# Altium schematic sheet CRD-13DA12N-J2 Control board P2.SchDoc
size 609 x 508 mm; SheetNumber: 1; SheetTotal: 3
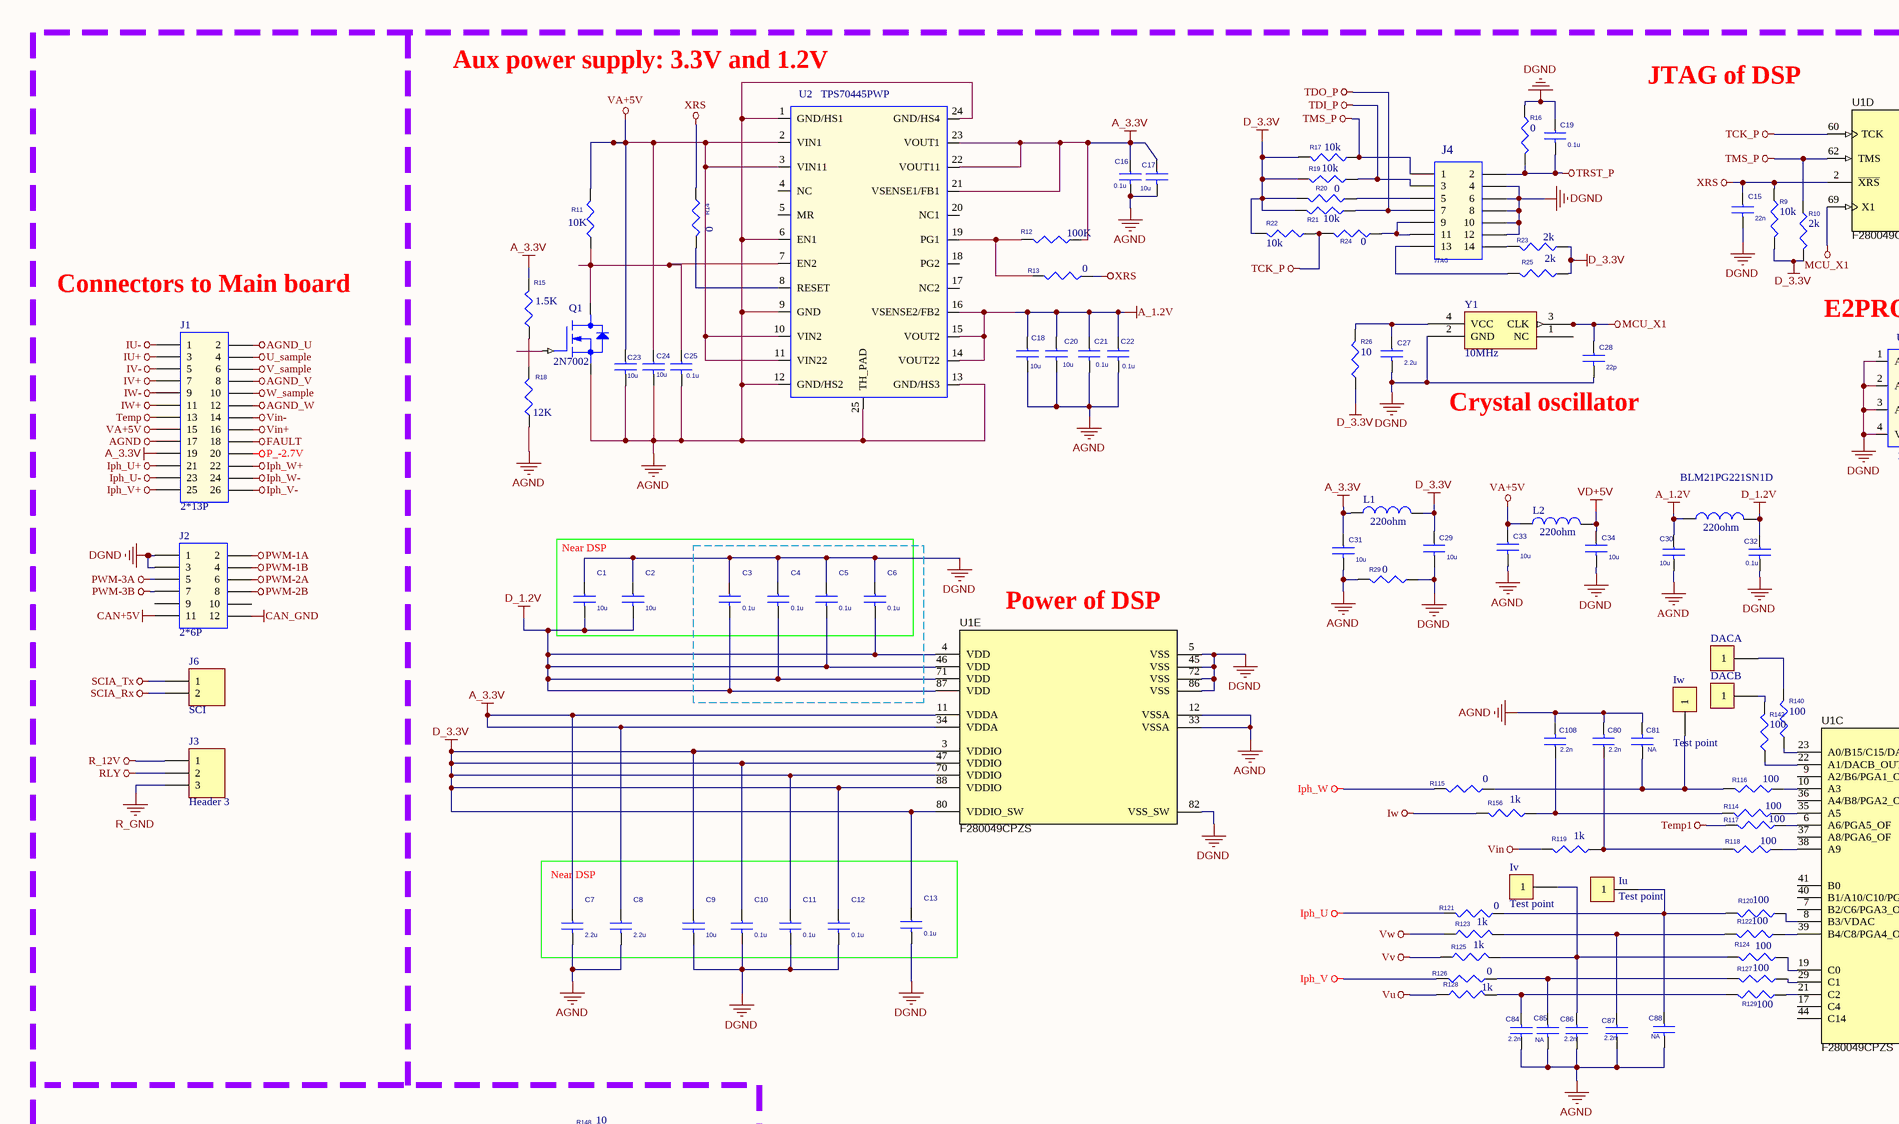
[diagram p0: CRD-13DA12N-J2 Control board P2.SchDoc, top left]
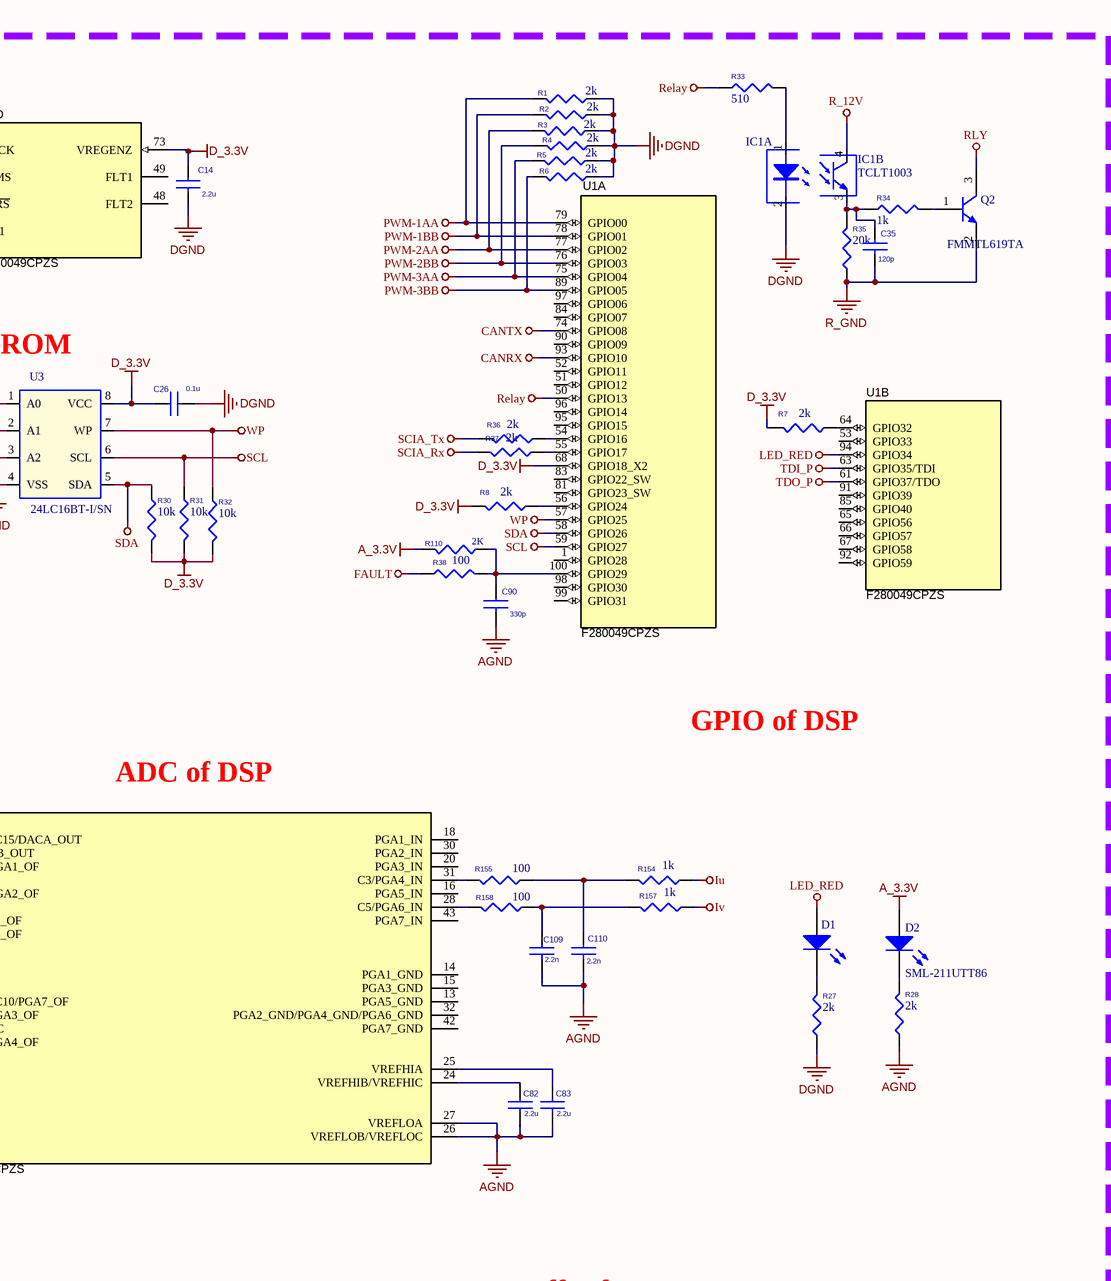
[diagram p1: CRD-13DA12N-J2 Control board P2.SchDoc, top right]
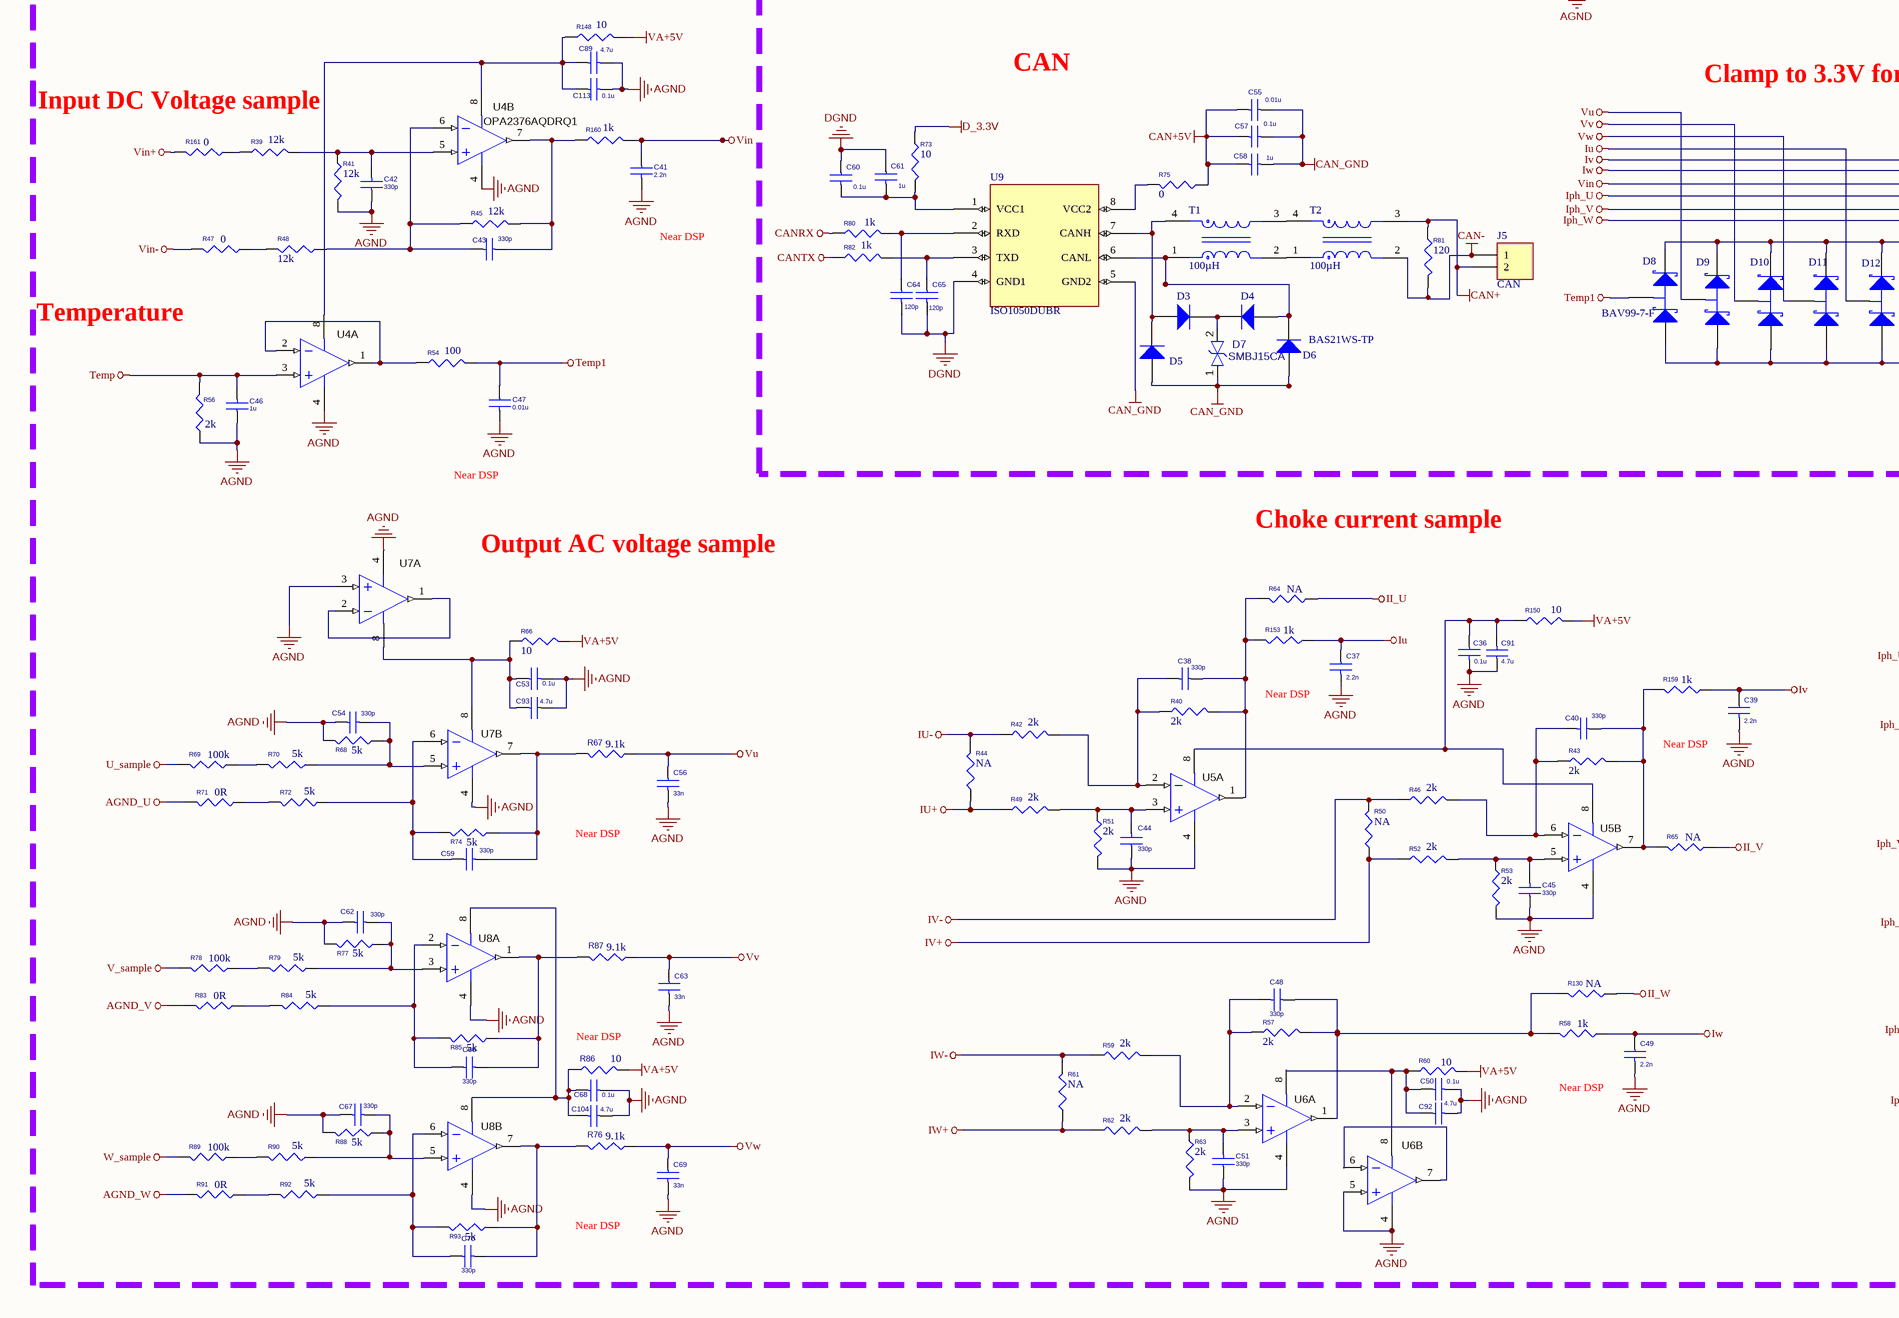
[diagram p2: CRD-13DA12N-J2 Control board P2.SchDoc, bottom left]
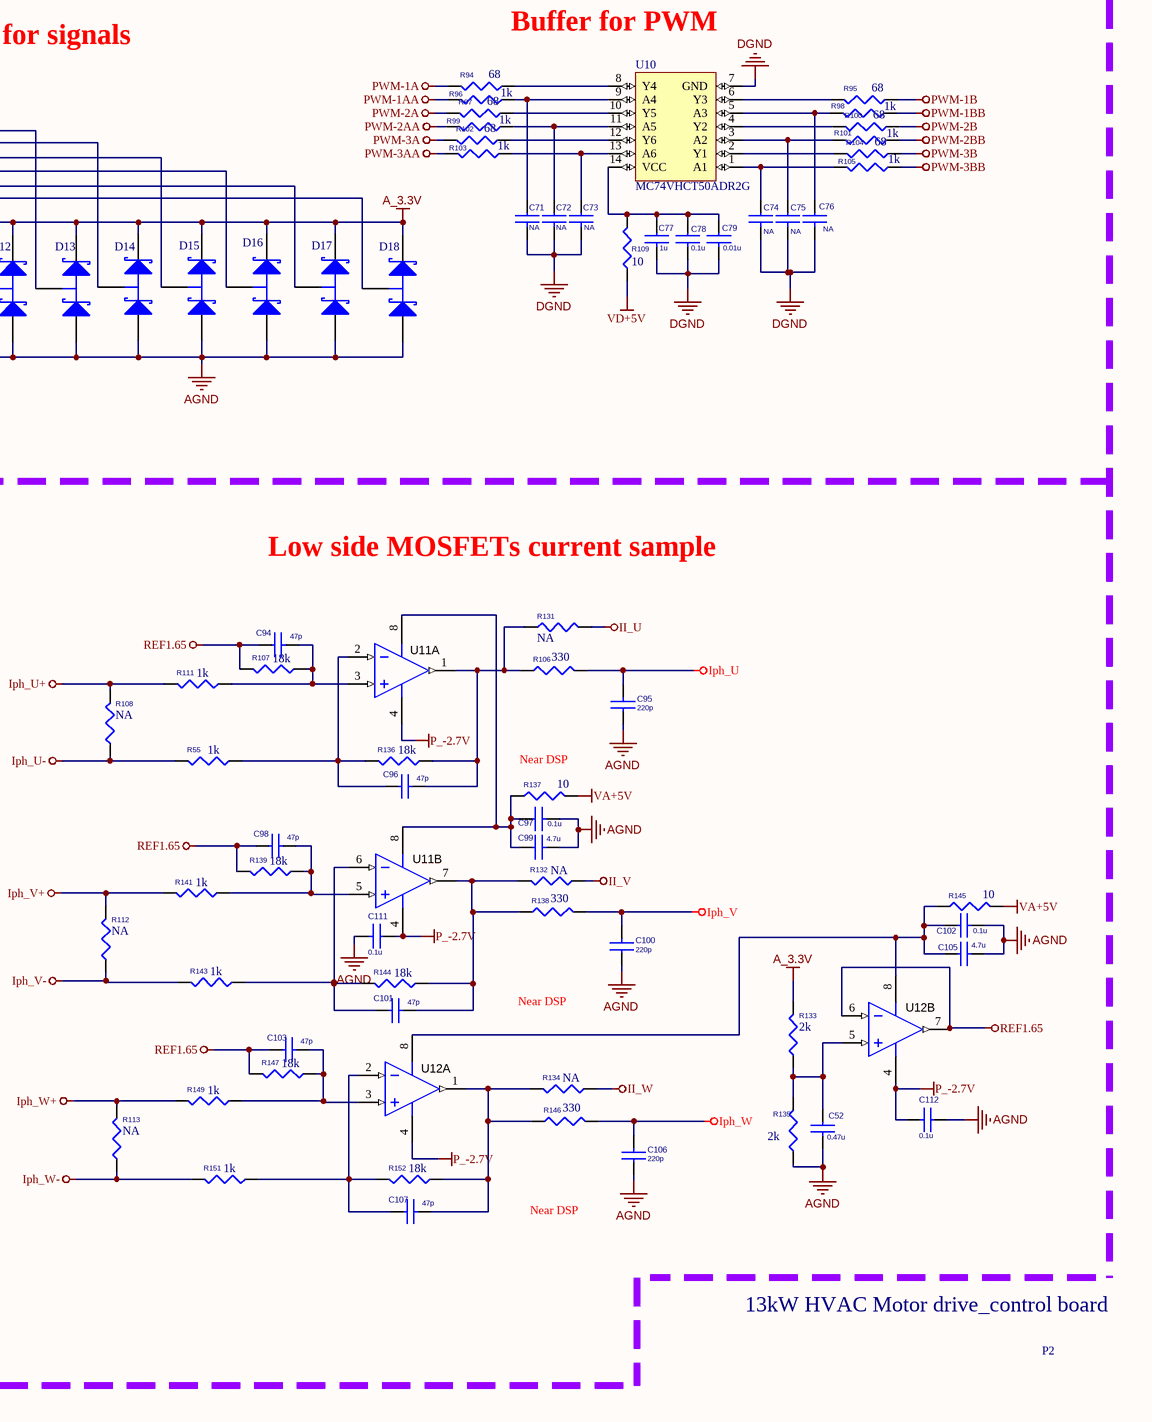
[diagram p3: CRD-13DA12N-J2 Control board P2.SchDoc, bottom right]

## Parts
C1  10u  [C0402]
C2  10u  [C0402]
C3  0.1u  [C0402]
C4  0.1u  [C0402]
C5  0.1u  [C0402]
C6  0.1u  [C0402]
C7  2.2u  [C0402]
C8  2.2u  [C0402]
C9  10u  [C0402]
C10  0.1u  [C0402]
C11  0.1u  [C0402]
C12  0.1u  [C0402]
C13  0.1u  [C0402]
C14  2.2u  [C0402]
C15  22n  [C0402]
C16  0.1u  [C0402]
C17  10u  [C0402]
C18  10u  [C0402]
C19  0.1u  [C0402]
C20  10u  [C0402]
C21  0.1u  [C0402]
C22  0.1u  [C0402]
C23  10u  [C0402]
C24  10u  [C0402]
C25  0.1u  [C0402]
C26  0.1u  [C0402]
C27  2.2u  [C0402]
C28  22p  [C0402]
C29  10u  [C0402]
C30  10u  [C0402]
C31  10u  [C0402]
C32  0.1u  [C0402]
C33  10u  [C0402]
C34  10u  [C0402]
C35  120p  [C0402]
C36  0.1u  [C0402]
C37  2.2n  [C0402]
C38  330p  [C0402]
C39  2.2n  [C0402]
C40  330p  [C0402]
C41  2.2n  [C0402]
C42  330p  [C0402]
C43  330p  [C0402]
C44  330p  [C0402]
C45  330p  [C0402]
C46  1u  [C0402]
C47  0.01u  [C0402]
C48  330p  [C0402]
C49  2.2n  [C0402]
C50  0.1u  [C0402]
C51  330p  [C0402]
C52  0.47u  [C0402]
C53  0.1u  [C0402]
C54  330p  [C0402]
C55  0.01u  [C0402]
C56  33n  [C0402]
C57  0.1u  [C0402]
C58  1u  [C0402]
C59  330p  [C0402]
C60  0.1u  [C0402]
C61  1u  [C0402]
C62  330p  [C0402]
C63  33n  [C0402]
C64  120p  [C0402]
C65  120p  [C0402]
C66  330p  [C0402]
C67  330p  [C0402]
C68  0.1u  [C0402]
C69  33n  [C0402]
C70  330p  [C0402]
C71  NA  [C0402]
C72  NA  [C0402]
C73  NA  [C0402]
C74  NA  [C0402]
C75  NA  [C0402]
C76  NA  [C0402]
C77  1u  [C0402]
C78  0.1u  [C0402]
C79  0.01u  [C0402]
C80  2.2n  [C0402]
C81  NA  [C0402]
C82  2.2u  [C0402]
C83  2.2u  [C0402]
C84  2.2n  [C0402]
C85  NA  [C0402]
C86  2.2n  [C0402]
C87  2.2n  [C0402]
C88  NA  [C0402]
C89  4.7u  [C0402]
C90  330p  [C0402]
C91  4.7u  [C0402]
C92  4.7u  [C0402]
C93  4.7u  [C0402]
C94  47p  [C0402]
C95  220p  [C0402]
C96  47p  [C0402]
C97  0.1u  [C0402]
C98  47p  [C0402]
C99  4.7u  [C0402]
C100  220p  [C0402]
C101  47p  [C0402]
C102  0.1u  [C0402]
C103  47p  [C0402]
C104  4.7u  [C0402]
C105  4.7u  [C0402]
C106  220p  [C0402]
C107  47p  [C0402]
C108  2.2n  [C0402]
C109  2.2n  [C0402]
C110  2.2n  [C0402]
C111  0.1u  [C0402]
C112  0.1u  [C0402]
C113  0.1u  [C0402]
D1  SML-211UTT86  [LED0805]  (value not drawn)
D2  SML-211UTT86  [LED0805]
D3  BAS21WS-TP  [DIOD-SOD323-2-A_V]  (value not drawn)
D4  BAS21WS-TP  [DIOD-SOD323-2-A_V]  (value not drawn)
D5  BAS21WS-TP  [DIOD-SOD323-2-A_V]  (value not drawn)
D6  BAS21WS-TP  [DIOD-SOD323-2-A_V]
D7  SMBJ15CA  [DO214AA]
D8  BAV99-7-F  [SOT-23-3]
D9  BAV99-7-F  [SOT-23-3]  (value not drawn)
D10  BAV99-7-F  [SOT-23-3]  (value not drawn)
D11  BAV99-7-F  [SOT-23-3]  (value not drawn)
D12  BAV99-7-F  [SOT-23-3]  (value not drawn)
D13  BAV99-7-F  [SOT-23-3]  (value not drawn)
D14  BAV99-7-F  [SOT-23-3]  (value not drawn)
D15  BAV99-7-F  [SOT-23-3]  (value not drawn)
D16  BAV99-7-F  [SOT-23-3]  (value not drawn)
D17  BAV99-7-F  [SOT-23-3]  (value not drawn)
D18  BAV99-7-F  [SOT-23-3]  (value not drawn)
DACA  Test point  [TEST_270X100_SMT]  (value not drawn)
DACB  Test point  [TEST_270X100_SMT]  (value not drawn)
IC1  TCLT1003  [tclt1003]  (value not drawn)  (parts A,B of 2)
Iu  Test point  [TEST_270X100_SMT]
Iv  Test point  [TEST_270X100_SMT]
Iw  Test point  [TEST_270X100_SMT]
J1  2*13P  [HDR2X13H-254MM-90-OP]
J2  2*6P  [HDR2X6H-254MM-90-OP]
J3  Header 3  [HDR1X3-254MM]
J4  JTAG  [HDR2X7H-254MM-90]
J5  CAN  [HDR1X2H-254MM]
J6  SCI  [HDR1X2H-254MM]
L1  value 220ohm  [6-0805_L]  (hidden comment: BLM21PG221SN1D)
L2  value 220ohm  [6-0805_L]  (hidden comment: BLM21PG221SN1D)
L3  BLM21PG221SN1D  value 220ohm  [6-0805_L]
Q1  2N7002  [SOT-23-3]
Q2  FMMTL619TA  [SOT-23-3]
R1  2k  [0402]
R2  2k  [0402]
R3  2k  [0402]
R4  2k  [0402]
R5  2k  [0402]
R6  2k  [0402]
R7  2k  [0402]
R8  2k  [0402]
R9  10k  [0402]
R10  2k  [0402]
R11  10K  [0402]
R12  100K  [0402]
R13  0  [0402]
R14  0  [0402]
R15  1.5K  [0402]
R16  0  [0402]
R17  10k  [0402]
R18  12K  [0402]
R19  10k  [0402]
R20  0  [0402]
R21  10k  [0402]
R22  10k  [0402]
R23  2k  [0402]
R24  0  [0402]
R25  2k  [0402]
R26  10  [0402]
R27  2k  [0402]
R28  2k  [0402]
R29  0  [0402]
R30  10k  [0402]
R31  10k  [0402]
R32  10k  [0402]
R33  510  [0402]
R34  1k  [0402]
R35  20k  [0402]
R36  2k  [0402]
R37  2k  [0402]
R38  100  [0402]
R39  12k  [R1206]
R40  2k  [0402]
R41  12k  [0402]
R42  2k  [0402]
R43  2k  [0402]
R44  NA  [0402]
R45  12k  [0402]
R46  2k  [0402]
R47  0  [R1206]
R48  12k  [R1206]
R49  2k  [0402]
R50  NA  [0402]
R51  2k  [0402]
R52  2k  [0402]
R53  2k  [0402]
R54  100  [0402]
R55  1k  [0402]
R56  2k  [0402]
R57  2k  [0402]
R58  1k  [0402]
R59  2k  [0402]
R60  10  [0402]
R61  NA  [0402]
R62  2k  [0402]
R63  2k  [0402]
R64  NA  [0402]
R65  NA  [0402]
R66  10  [0402]
R67  9.1k  [0402]
R68  5k  [0402]
R69  100k  [R1206]
R70  5k  [R1206]
R71  0R  [R1206]
R72  5k  [R1206]
R73  10  [0402]
R74  5k  [0402]
R75  0  [0402]
R76  9.1k  [0402]
R77  5k  [0402]
R78  100k  [R1206]
R79  5k  [R1206]
R80  1k  [0402]
R81  120  [R0603]
R82  1k  [0402]
R83  0R  [R1206]
R84  5k  [R1206]
R85  5k  [0402]
R86  10  [0402]
R87  9.1k  [0402]
R88  5k  [0402]
R89  100k  [R1206]
R90  5k  [R1206]
R91  0R  [R1206]
R92  5k  [R1206]
R93  5k  [0402]
R94  68  [0402]
R95  68  [0402]
R96  1k  [0402]
R97  68  [0402]
R98  1k  [0402]
R99  1k  [0402]
R100  68  [0402]
R101  1k  [0402]
R102  68  [0402]
R103  1k  [0402]
R104  68  [0402]
R105  1k  [0402]
R106  330  [0402]
R107  18k  [0402]
R108  NA  [0402]
R109  10  [0402]
R110  2K  [0402]
R111  1k  [0402]
R112  NA  [0402]
R113  NA  [0402]
R114  100  [0402]
R115  0  [0402]
R116  100  [0402]
R117  100  [0402]
R118  100  [0402]
R119  1k  [0402]
R120  100  [0402]
R121  0  [0402]
R122  100  [0402]
R123  1k  [0402]
R124  100  [0402]
R125  1k  [0402]
R126  0  [0402]
R127  100  [0402]
R128  1k  [0402]
R129  100  [0402]
R130  NA  [0402]
R131  NA  [0402]
R132  NA  [0402]
R133  2k  [0402]
R134  NA  [0402]
R135  2k  [0402]
R136  18k  [0402]
R137  10  [0402]
R138  330  [0402]
R139  18k  [0402]
R140  100  [0402]
R141  1k  [0402]
R142  100  [0402]
R143  1k  [0402]
R144  18k  [0402]
R145  10  [0402]
R146  330  [0402]
R147  18k  [0402]
R148  10  [0402]
R149  1k  [0402]
R150  10  [0402]
R151  1k  [0402]
R152  18k  [0402]
R153  1k  [0402]
R154  1k  [0402]
R155  100  [0402]
R156  1k  [0402]
R157  1k  [0402]
R158  100  [0402]
R159  1k  [0402]
R160  1k  [0402]
R161  0  [R1206]
T1  AMCW4532B-2-101T: 100µH  [T1-1812]  (hidden comment: DLW43SH101XK2L)
T2  AMCW4532B-2-101T: 100µH  [T1-1812]  (hidden comment: DLW43SH101XK2L)
U1  F280049CPZS  [PZ0100A_N]  (parts A,B,C,D,E of 5)
U2  TPS70445PWP  [TPS70445PWP]
U3  24LC16BT-I/SN  [8SOIC]
U4  OPA2376AQDRQ1  [8SOIC]  (value not drawn)  (parts A,B of 2)
U5  OPA2376AQDRQ1  [8SOIC]  (value not drawn)  (parts A,B of 2)
U6  OPA2376AQDRQ1  [8SOIC]  (value not drawn)  (parts A,B of 2)
U7  OPA2376AQDRQ1  [8SOIC]  (value not drawn)  (parts A,B of 2)
U8  OPA2376AQDRQ1  [8SOIC]  (value not drawn)  (parts A,B of 2)
U9  ISO1050DUBR  [8-SOP]
U10  MC74VHCT50ADR2G  [14SOIC]
U11  OPA2836IDR  [8SOIC]  (value not drawn)  (parts A,B of 2)
U12  OPA2836IDR  [8SOIC]  (value not drawn)  (parts A,B of 2)
Y1  10MHz  [TBD-Footprint-1]

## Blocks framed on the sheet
Near DSP: C1-C6
Near DSP: C7-C13

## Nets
A_1.2V: C18.1 C20.1 C21.1 C22.1 C30.1 L3.1 U2.14(VOUT22) U2.15(VOUT2) U2.16(VSENSE2/FB2)
A_3.3V: C7.1 C8.1 C16.1 C17.1 C31.1 D2.1(A) D8.2(K) D9.2(K) D10.2(K) D11.2(K) D12.2(K) D13.2(K) D14.2(K) D15.2(K) D16.2(K) D17.2(K) D18.2(K) J1.19 L1.1 R12.1 R15.2 R110.2 R133.2 U1.11(VDDA) U1.34(VDDA) U2.21(VSENSE1/FB1) U2.22(VOUT11) U2.23(VOUT1)
AGND: C7.2 C8.2 C16.2 C17.2 C18.2 C20.2 C21.2 C22.2 C23.2 C24.2 C25.2 C30.2 C31.2 C33.2 C36.2 C37.2 C39.2 C41.2 C42.1 C44.1 C45.1 C46.1 C47.2 C49.2 C50.2 C51.1 C52.2 C53.2 C54.1 C56.2 C62.1 C63.2 C67.1 C68.2 C69.2 C80.2 C81.2 C82.2 C83.2 C84.2 C85.2 C86.2 C87.2 C88.2 C89.2 C90.2 C91.1 C92.2 C93.2 C95.1 C97.2 C99.2 C100.1 C102.2 C104.2 C105.2 C106.1 C108.2 C109.2 C110.2 C111.2 C112.1 C113.2 D8.1(A) D9.1(A) D10.1(A) D11.1(A) D12.1(A) D13.1(A) D14.1(A) D15.1(A) D16.1(A) D17.1(A) D18.1(A) J1.17 Q1.2(SOURCE) R18.1 R28.1 R29.2 R41.2 R51.2 R53.2 R56.1 R63.2 R68.2 R77.2 R88.2 R135.1 U1.12(VSSA) U1.26(VREFLOB/VREFLOC) U1.27(VREFLOA) U1.33(VSSA) U2.1(GND/HS1) U2.6(EN1) U2.9(GND) U2.12(GND/HS2) U2.13(GND/HS3) U2.24(GND/HS4) U2.25(TH_PAD) U4.4(V-) U5.4(V-) U6.4(V-) U6.5(IN_B+) U7.3(IN_A+) U7.4(V-) U8.4(V-)
AGND_U: J1.2 R71.2
AGND_V: J1.8 R83.2
AGND_W: J1.12 R91.2
CAN+: J5.2 R81.1 T2.3
CAN+5V: C55.1 C57.1 C58.1 J2.11 R75.1
CAN-: J5.1 R81.2 T2.2
CAN_GND: C55.2 C57.2 C58.2 D5.1(A) D6.1(A) D7.1(A) J2.12 U9.5(GND2)
CANRX: R80.1 U1.93(GPIO10)
CANTX: R82.1 U1.74(GPIO08)
D_1.2V: C1.2 C2.2 C3.2 C4.2 C5.2 C6.2 C32.1 L3.2 U1.4(VDD) U1.46(VDD) U1.71(VDD) U1.87(VDD)
D_3.3V: C9.1 C10.1 C11.1 C12.1 C13.1 C14.1 C26.1 C29.1 L1.2 R7.2 R8.2 R9.2 R10.2 R17.2 R19.2 R20.2 R21.2 R22.2 R23.1 R25.1 R26.1 R30.2 R31.2 R32.2 R73.1 U1.3(VDDIO) U1.47(VDDIO) U1.68(GPIO18_X2) U1.70(VDDIO) U1.73(VREGENZ) U1.80(VDDIO_SW) U1.88(VDDIO) U3.8(VCC)
DGND: C1.1 C2.1 C3.1 C4.1 C5.1 C6.1 C9.2 C10.2 C11.2 C12.2 C13.2 C14.2 C15.2 C19.1 C26.2 C27.2 C28.2 C29.2 C32.2 C34.2 C60.1 C61.1 C64.2 C65.2 C71.2 C72.2 C73.2 C74.2 C75.2 C76.2 C77.2 C78.2 C79.2 IC1.2 J2.1 J2.3 J4.4 J4.6 J4.8 J4.10 J4.12 R1.1 R2.1 R3.1 R4.1 R5.1 R6.1 R16.1 R27.1 R29.1 U1.5(VSS) U1.45(VSS) U1.72(VSS) U1.82(VSS_SW) U1.86(VSS) U3.1(A0) U3.2(A1) U3.3(A2) U3.4(VSS) U9.4(GND1) U10.7(GND) Y1.2(GND)
FAULT: J1.18 R38.1
II_U: R64.1 R131.2
II_V: R65.1 R132.1
II_W: R130.1 R134.1
Iph_U: C95.2 D16.3(C) R106.2 R121.2
Iph_U+: J1.21 R108.2 R111.2
Iph_U-: J1.23 R55.2 R108.1
Iph_V: C100.2 D17.3(C) R126.2 R138.2
Iph_V+: J1.25 R112.2 R141.2
Iph_V-: J1.26 R112.1 R143.2
Iph_W: C106.2 D18.3(C) R115.2 R146.2
Iph_W+: J1.22 R113.2 R149.2
Iph_W-: J1.24 R113.1 R151.2
Iu: C37.1 D12.3(C) R153.1 R154.1
IU+: J1.3 R44.1 R49.1
IU-: J1.1 R42.1 R44.2
Iv: C39.1 D13.3(C) R157.1 R159.1
IV+: J1.7 R50.1 R52.1
IV-: J1.5 R46.1 R50.2
Iw: C49.1 D14.3(C) R58.1 R156.2
IW+: J1.11 R61.1 R62.1
IW-: J1.9 R59.1 R61.2
LED_RED: D1.1(A) U1.94(GPIO34)
MCU_X1: C28.1 U1.69(X1) Y1.3(CLK)
P_-2.7V: C111.1 C112.2 J1.20 U11.4(V-) U12.4(V-)
PWM-1A: J2.2 R94.2
PWM-1AA: R1.2 R96.1 U1.79(GPIO00)
PWM-1B: J2.4 R95.1
PWM-1BB: R2.2 R98.1 U1.78(GPIO01)
PWM-2A: J2.6 R97.2
PWM-2AA: R3.2 R99.1 U1.77(GPIO02)
PWM-2B: J2.8 R100.1
PWM-2BB: R4.2 R101.1 U1.76(GPIO03)
PWM-3A: J2.5 R102.2
PWM-3AA: R5.2 R103.1 U1.75(GPIO04)
PWM-3B: J2.7 R104.1
PWM-3BB: R6.2 R105.2 U1.89(GPIO05)
R_12V: IC1.4 J3.1
R_GND: C35.2 J3.3 Q2.2 R35.1
REF1.65: C94.1 C98.1 C103.1 R107.2 R139.2 R147.2 U12.6(IN_B-) U12.7(OUT_B)
Relay: R33.1 U1.50(GPIO13)
RLY: J3.2 Q2.3
SCIA_Rx: J6.2 R37.2
SCIA_Tx: J6.1 R36.2
SCL: R31.1 U1.59(GPIO27) U3.6(SCL)
SDA: R30.1 U1.58(GPIO26) U3.5(SDA)
TCK_P: R22.1 R24.2 U1.60(TCK)
TDI_P: J4.3 R19.1 U1.63(GPIO35/TDI)
TDO_P: J4.7 R21.1 U1.61(GPIO37/TDO)
Temp: C46.2 J1.13 R56.2 U4.3(IN_A+)
Temp1: C47.1 D8.3(C) R54.2 R117.2
TMS_P: J4.1 R10.1 R17.1 U1.62(TMS)
TRST_P: C19.2 J4.2 R16.2
U_sample: J1.4 R69.2
V_sample: J1.6 R78.2
VA+5V: C23.1 C24.1 C33.1 J1.15 L2.1 R11.2 R60.2 R66.2 R86.2 R137.2 R145.2 R148.2 R150.2 U2.2(VIN1) U2.3(VIN11) U2.10(VIN2) U2.11(VIN22)
VD+5V: C34.1 L2.2 R109.1
Vin: C41.1 D15.3(C) R119.2 R160.2
Vin+: J1.16 R161.2
Vin-: J1.14 R47.2
Vu: C56.1 D9.3(C) R67.1 R128.2
Vv: C63.1 D10.3(C) R87.1 R125.2
Vw: C69.1 D11.3(C) R76.1 R123.2
W_sample: J1.10 R89.2
WP: R32.1 U1.57(GPIO25) U3.7(WP)
XRS: C15.1 R9.1 R13.1 R14.1 U1.2(~{XRS})
NetC25_1: C25.1 Q1.3(DRAIN) R11.1 U2.7(EN2)
NetC27_1: C27.1 R26.2 Y1.4(VCC)
NetC35_1: C35.1 IC1.3 R34.1 R35.2
NetC36_1: C36.1 C91.2 R150.1 U5.8(V+)
NetC38_1: C38.1 R40.2 R64.2 R153.2 U5.1(OUT_A)
NetC38_2: C38.2 R40.1 R42.2 U5.2(IN_A-)
NetC40_1: C40.1 R43.2 R65.2 R159.2 U5.7(OUT_B)
NetC40_2: C40.2 R43.1 R46.2 U5.6(IN_B-)
NetC42_2: C42.2 R39.2 R41.1 U4.5(IN_B+)
NetC43_1: C43.1 R45.2 R160.1 U4.7(OUT_B)
NetC43_2: C43.2 R45.1 R48.1 U4.6(IN_B-)
NetC44_2: C44.2 R49.2 R51.1 U5.3(IN_A+)
NetC45_2: C45.2 R52.2 R53.1 U5.5(IN_B+)
NetC48_1: C48.1 R57.2 R58.2 R130.2 U6.1(OUT_A)
NetC48_2: C48.2 R57.1 R59.2 U6.2(IN_A-)
NetC50_1: C50.1 C92.1 R60.1 U6.8(V+)
NetC51_2: C51.2 R62.2 R63.1 U6.3(IN_A+)
NetC52_1: C52.1 R133.1 R135.2 U12.5(IN_B+)
NetC53_1: C53.1 C93.1 R66.1 U7.8(V+)
NetC54_2: C54.2 R68.1 R70.1 U7.5(IN_B+)
NetC59_1: C59.1 R72.1 R74.2 U7.6(IN_B-)
NetC59_2: C59.2 R67.2 R74.1 U7.7(OUT_B)
NetC60_2: C60.2 C61.2 R73.2 U9.1(VCC1)
NetC62_2: C62.2 R77.1 R79.1 U8.3(IN_A+)
NetC64_1: C64.1 R80.2 U9.2(RXD)
NetC65_1: C65.1 R82.2 U9.3(TXD)
NetC66_1: C66.1 R84.1 R85.2 U8.2(IN_A-)
NetC66_2: C66.2 R85.1 R87.2 U8.1(OUT_A)
NetC67_2: C67.2 R88.1 R90.1 U8.5(IN_B+)
NetC68_1: C68.1 C104.1 R86.1 U8.8(V+)
NetC70_1: C70.1 R92.1 R93.2 U8.6(IN_B-)
NetC70_2: C70.2 R76.2 R93.1 U8.7(OUT_B)
NetC71_1: C71.1 R96.2 U10.9(A4)
NetC72_1: C72.1 R99.2 U10.11(A5)
NetC73_1: C73.1 R103.2 U10.13(A6)
NetC74_1: C74.1 R105.1 U10.1(A1)
NetC75_1: C75.1 R101.2 U10.3(A2)
NetC76_1: C76.1 R98.2 U10.5(A3)
NetC77_1: C77.1 C78.1 C79.1 R109.2 U10.14(VCC)
NetC80_1: C80.1 R118.2 R119.1
NetC81_1: C81.1 Iw.1 R115.1 R116.2
NetC82_1: C82.1 U1.24(VREFHIB/VREFHIC)
NetC83_1: C83.1 U1.25(VREFHIA)
NetC84_1: C84.1 R128.1 R129.2
NetC85_1: C85.1 R126.1 R127.2
NetC86_1: C86.1 Iv.1 R124.2 R125.1
NetC87_1: C87.1 R122.2 R123.1
NetC88_1: C88.1 Iu.1 R120.2 R121.1
NetC89_1: C89.1 C113.1 R148.1 U4.8(V+)
NetC90_1: C90.1 R38.2 R110.1 U1.100(GPIO29)
NetC94_2: C94.2 R107.1 R111.1 U11.3(IN_A+)
NetC96_1: C96.1 R55.1 R136.2 U11.2(IN_A-)
NetC96_2: C96.2 R106.1 R131.1 R136.1 U11.1(OUT_A)
NetC97_1: C97.1 C99.1 R137.1 U11.8(V+)
NetC98_2: C98.2 R139.1 R141.1 U11.5(IN_B+)
NetC101_1: C101.1 R143.1 R144.2 U11.6(IN_B-)
NetC101_2: C101.2 R132.2 R138.1 R144.1 U11.7(OUT_B)
NetC102_1: C102.1 C105.1 R145.1 U12.8(V+)
NetC103_2: C103.2 R147.1 R149.1 U12.3(IN_A+)
NetC107_1: C107.1 R151.1 R152.2 U12.2(IN_A-)
NetC107_2: C107.2 R134.2 R146.1 R152.1 U12.1(OUT_A)
NetC108_1: C108.1 R114.2 R156.1
NetC109_1: C109.1 R157.2 R158.1
NetC110_1: C110.1 R154.2 R155.1
NetD1_2: D1.2(K) R27.2
NetD2_2: D2.2(K) R28.2
NetD3_1: D3.1(A) D5.2(K) T1.4 U9.7(CANH)
NetD3_2: D3.2(K) D4.2(K) D7.2(A)
NetD4_1: D4.1(A) D6.2(K) T1.1 U9.6(CANL)
NetDACA_1: DACA.1 R140.2
NetDACB_1: DACB.1 R142.2
NetIC1_1: IC1.1 R33.2
NetJ4_5: J4.5 R20.1
NetJ4_9: J4.9 J4.11 R24.1
NetJ4_13: J4.13 R25.2
NetJ4_14: J4.14 R23.2
NetQ2_1: Q2.1 R34.2
NetR7_1: R7.1 U1.64(GPIO32)
NetR8_1: R8.1 U1.56(GPIO24)
NetR12_2: R12.2 R13.2 U2.19(PG1)
NetR14_2: R14.2 U2.8(RESET)
NetR15_1: R15.1 R18.2
NetR36_1: R36.1 U1.54(GPIO16)
NetR37_1: R37.1 U1.55(GPIO17)
NetR39_1: R39.1 R161.1
NetR47_1: R47.1 R48.2
NetR54_1: R54.1 U4.1(OUT_A) U4.2(IN_A-)
NetR69_1: R69.1 R70.2
NetR71_1: R71.1 R72.2
NetR75_2: R75.2 U9.8(VCC2)
NetR78_1: R78.1 R79.2
NetR83_1: R83.1 R84.2
NetR89_1: R89.1 R90.2
NetR91_1: R91.1 R92.2
NetR94_1: R94.1 U10.8(Y4)
NetR95_2: R95.2 U10.6(Y3)
NetR97_1: R97.1 U10.10(Y5)
NetR100_2: R100.2 U10.4(Y2)
NetR102_1: R102.1 U10.12(Y6)
NetR104_2: R104.2 U10.2(Y1)
NetR114_1: R114.1 U1.35(A5)
NetR116_1: R116.1 U1.10(A3)
NetR117_1: R117.1 U1.6(A6/PGA5_OF)
NetR118_1: R118.1 U1.38(A9)
NetR120_1: R120.1 U1.8(B3/VDAC)
NetR122_1: R122.1 U1.39(B4/C8/PGA4_OF)
NetR124_1: R124.1 U1.19(C0)
NetR127_1: R127.1 U1.29(C1)
NetR129_1: R129.1 U1.21(C2)
NetR140_1: R140.1 U1.23(A0/B15/C15/DACA_OUT)
NetR142_1: R142.1 U1.22(A1/DACB_OUT)
NetR155_2: R155.2 U1.31(C3/PGA4_IN)
NetR158_2: R158.2 U1.28(C5/PGA6_IN)
NetT1_2: T1.2 T2.1
NetT1_3: T1.3 T2.4
NetU6_6: U6.6(IN_B-) U6.7(OUT_B)
NetU7_1: U7.1(OUT_A) U7.2(IN_A-)

Not connected (* = marked no-connect by the designer): J2 9 10; Q1 1(GATE); U1 1(GPIO28) 7(B2/C6/PGA3_OF) 9(A2/B6/PGA1_OF) 13(PGA5_GND) 14(PGA1_GND) 15(PGA3_GND) 16(PGA5_IN) 17(C4) 18(PGA1_IN) 20(PGA3_IN) 30(PGA2_IN) 32(PGA2_GND/PGA4_GND/PGA6_GND) 36(A4/B8/PGA2_OF) 37(A8/PGA6_OF) 40(B1/A10/C10/PGA7_OF) 41(B0) 42(PGA7_GND) 43(PGA7_IN) 44(C14) 48(FLT2) 49(FLT1) 51(GPIO12) 52(GPIO11) 53(GPIO33) 65(GPIO56) 66(GPIO57) 67(GPIO58) 81(GPIO23_SW) 83(GPIO22_SW) 84(GPIO07) 85(GPIO40) 90(GPIO09) 91(GPIO39) 92(GPIO59) 95(GPIO15) 96(GPIO14) 97(GPIO06) 98(GPIO30) 99(GPIO31); U2 4(NC) 5(MR) 17(NC2) 18(PG2) 20(NC1); Y1 1(NC)

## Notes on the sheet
- (near U2) Aux power supply: 3.3V and 1.2V
- JTAG of DSP
- (near J1) Connectors to Main board
- E2PROM
- (near C28) Crystal oscillator
- (near U1) Power of DSP
- GPIO of DSP
- (near U1) ADC of DSP
- Buffer for PWM
- Input DC Voltage sample
- CAN
- Clamp to 3.3V for signals
- Near DSP
- Temperature
- Output AC voltage sample
- Choke current sample
- Low side MOSFETs current sample
- (near R137) Near DSP
- (near R86) Near DSP
- 13kW HVAC Motor drive_control board
- P2

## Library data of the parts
C1 C2 C9 C17 C18 C20 C23 C24 C29-C31 C33 C34 = CAP NP_Dup1: CAP CER 10UF 10V X5R 0402; PartNumber: CL05A106MP5NUNC; Manufactur: Samsung Electro-Mechanics
C3-C6 C10-C13 C16 C19 C21 C22 C25 C26 C32 C36 C50 C53 C57 C60 C68 C78 C97 C102 C111-C113 = CAP NP_Dup1: CAP CER 0.1UF 25V X7R 0402; PartNumber: C0402C104K3RAC7867; Manufactur: KEMET
C7 C8 C14 C27 C82 C83 = CAP NP_Dup1: CAP CER 2.2UF 10V X5R 0402; Manufactur: KEMET; PartNumber: C0402C225M8PAC7867
C15 = CAP NP_Dup1: CAP CER 0.022UF 50V X7R 0402; PartNumber: C0402C223K5RAC7411; Manufactur: KEMET
C28 = CAP NP_Dup1: CAP CER 22PF 50V C0G/NP0 0402; PartNumber: C0402C220J5GAC7411; Manufactur: KEMET
C35 C64 C65 = CAP NP_Dup1: CAP CER 120PF 25V C0G/NP0 0402; PartNumber: C0402C121J3GAC7867; Manufactur: KEMET
C37 C39 C41 C49 C80 C81 C84-C88 C108-C110 = CAP NP_Dup1: CAP CER 2200PF 50V X7R 0402; PartNumber: C0402C222K5RAC7867; Manufactur: KEMET
C38 C40 C42-C45 C48 C51 C54 C59 C62 C66 C67 C70 = CAP NP_Dup1: CAP CER 330PF 25V X7R 0402; PartNumber: C0402C331K3RAC7867; Manufactur: KEMET
C46 C58 C61 C77 = CAP NP_Dup1: CAP CER 1UF 10V X5R 0402; PartNumber: C0402C105K8PAC7411; Manufactur: KEMET
C47 C55 C79 = CAP NP_Dup1: CAP CER 0.012UF 16V X7R 0402; PartNumber: C0402C123K4RAC7867; Manufactur: KEMET
C52 = CAP NP_Dup1: CAP CER 0.47UF 25V X5R 0402; PartNumber: C1005X5R1E474K050BB; Manufactur: TDK
C56 C63 C69 = CAP NP_Dup1: CAP CER 0.033uF 25V X7R 0402; PartNumber: C0402C333K3RECTU; Manufactur: KEMET
C71-C76 = CAP NP_Dup1: CAP CER 100PF 25V X7R 0402; Manufactur: KEMET; PartNumber: C0402C101K3RAC7867
C89 C91-C93 C99 C104 C105 = CAP NP_Dup1: CAP CER 4.7UF 10V X5R 0402; PartNumber: CL05A475MP5NRNC; Manufactur: Samsung Electro-Mechanics
C90 = CAP NP_Dup1: CAP CER 330PF 25V C0G/NP0 0402; PartNumber: C0402C331J3GAC7867; Manufactur: KEMET
C94 C96 C98 C101 C103 C107 = CAP NP_Dup1: CAP CER 47PF 25V X7R 0402; PartNumber: C0402C470K3RAC7867; Manufactur: KEMET
C95 C100 C106 = CAP NP_Dup1: CAP CER 220PF 25V X7R 0402; PartNumber: C0402C221K3RAC7867; Manufactur: KEMET
D1 D2 = LED0: LED RED CLEAR 0805 SMD; Manufactur: Rohm Semiconductor
D3-D6 = CMP-004-00002-1: DIODE GEN PURP 250V 200MA SOD323; Manufacturer: Diodes Inc; Manufactur: Micro Commercial Co; Peak Reverse Current: 1uA; Forward Voltage: 1.25V; Recovery Time: 4ns; Max Surge Current: 2A; Forward Current: 3dA; Elements: 1
D7 = CMP-004-00030-2: TVS DIODE 15V 24.4V DO214AA; Manufactur: Littelfuse Inc.; Manufacturer Part Number: ESDALC5-1BM2
D8-D18 = CMP-004-00011-1: DIODE ARRAY GP 75V 300MA SOT23-3; Manufacturer: Diodes Inc; Manufacturer: Diodes; Manufacturer Part Number: BAS70-04-7-F; Manufactur: Micro Commercial Co; Power: 200mW; Peak Reverse Current: 0.1uA; Forward Voltage: 1V; Element Configuration: CommonCathode; Recovery Time: 5ns; Max Surge Current: 1dA; Forward Current: 70mA; Elements: 2
DACA DACB Iu Iv Iw = Test
IC1 = IC-PC817: OPTOISOLATR 5KV TRANSISTOR 4-SOP; Manufactur: VISHAY
J1 = 2*13P: CONN HEADER R/A 26POS 2.54MM; PartNumber: PH2RA-26-UA; Manufactur: Adam Tech
J2 = 2*6P: CONN HEADER R/A 12POS 2.54MM; Manufactur: Adam Tech; PartNumber: PH2RA-12-UA
J3 = Header 3: CONN HEADER R/A 3POS 2.54MM
J4 = 2*7P: CONN HEADER R/A 14POS 2.54MM; Part number: 621000812; Part_Name: Á¬½ÓÆ÷; Part Label: 2*7P 2.54 Ö±Õë; Manufactur: Adam Tech; PartNumber: PH2RA-14-UA; PCB Footprint: con_2mm54_7x2; Unit: PCS
J5 J6 = Header 2H: CONN HEADER R/A 2POS 2.54MM; Manufactur: Adam Tech; PartNumber: PH2RA-02-UA
L1-L3 = Inductor: FERRITE BEAD 220 OHM 0805 1LN; Manufactur: Murata Electronics; Code_IEC: 1005
Q1 = 2N7002/SOT: MOSFET N-CH 60V 115MA SOT-23; Manufactur: onsemi
Q2 = 2N3904: TRANS NPN 40V 0.6A SOT23-3; Manufactur: Diodes
R1 R6 = RESISTOR_Dup1: RCC0402 100 2K0 1% ET7 E3; Manufacturer: Vishay Dale; PartNumber: RCC04022K00FKED; PCB Footprint: R0402; Parameter 3: KEMET
R2 R3 R5 R10 R23 R25 R27 R28 R40 R42 R43 R46 R49 R51-R53 R56 R57 R59 R62 R63 R133 R135 = RESISTOR_Dup1: RCC0402 100 2K0 1% ET7 E3; PartNumber: RCC04022K00FKED; PCB Footprint: R0402; Parameter 1: Vishay Dale; Parameter 3: KEMET
R4 = RESISTOR_Dup1: RCC0402 100 2K0 1% ET7 E3; PartNumber: RCC04022K00FKED; PCB Footprint: R0402; Parameter 1: Vishay Dale
R7 R8 R36 R37 = RESISTOR_Dup1: RCC0402 100 2K0 1% ET7 E3; Manufacturer: Vishay Dale; PartNumber: RCC04022K00FKED; PCB Footprint: R0402
R9 R17 R19 R21 R22 R30-R32 = RESISTOR_Dup1: RCC0402 100 10K 1% ET7 E3; PartNumber: RCC040210K0FKED; Manufactur: Vishay Dale; PCB Footprint: R0402
R11 = RESISTOR_Dup1: RCC0402 100 10K 1% ET7 E3; PartNumber: RCC040210K0FKED; Manufactur: Vishay Dale; PCB Footprint: R0402; Parameter 3: KEMET
R12 = RESISTOR_Dup1: RCC0402 100 100K 1% ET7 E3; PartNumber: RCC0402100KFKED; Manufactur: Vishay Dale; PCB Footprint: R0402
R13 R14 R16 R20 R24 R29 R75 = RESISTOR_Dup1: RCC0402 0R0 ET7 E3; Manufactur: Vishay Dale; PartNumber: RCC04020000Z0ED; PCB Footprint: R0402
R15 = RESISTOR_Dup1: RCC0402 100 1K5 1% ET7 E3; Manufactur: Vishay Dale; PartNumber: RCC04021K50FKED; PCB Footprint: R0402
R18 R41 R45 = RESISTOR_Dup1: RES SMD 12K OHM 1% 1/5W 0402; PartNumber: RCS040212K0FKED; Manufactur: Vishay Dale; PCB Footprint: R0402; Parameter 3: KEMET
R26 R60 R66 R73 R86 R109 R137 R145 R148 R150 = RESISTOR_Dup1: RCC0402 100 10R 1% ET7 E3; PartNumber: RCC040210R0FKED; Manufactur: Vishay Dale; PCB Footprint: R0402; Parameter 3: KEMET
R33 = RESISTOR_Dup1: RES 510 OHM 1% 1/16W 0402; PartNumber: RC0402FR-07510RL; Manufactur: YAGEO; PCB Footprint: R0402
R34 R58 R64 R65 R80 R82 R96 R98 R99 R101 R103 R105 R119 R123 R125 R128 R130-R132 R134 R153 R154 R156 R157 R159 R160 = RESISTOR_Dup1: RCC0402 100 1K0 1% ET7 E3; PartNumber: RCC04021K00FKED; Manufactur: Vishay Dale; PCB Footprint: R0402; Parameter 3: KEMET
R35 = RESISTOR_Dup1: RCC0402 100 20K0 1% ET7 E3; PartNumber: RCC040220K00FKED; Manufactur: Vishay Dale; PCB Footprint: R0402; Parameter 3: KEMET
R38 R54 R114 R116-R118 R120 R122 R124 R127 R129 R140 R142 R155 R158 = RESISTOR_Dup1: RCC0402 100 100R 1% ET7 E3; PartNumber: RCC0402100RFKED; Manufactur: Vishay Dale; PCB Footprint: R0402; Parameter 3: KEMET
R39 R48 = RESISTOR_Dup1: ES SMD 12K OHM 1% 1/4W 1206; PartNumber: CRCW120612K0FHTAP; Manufactur: Vishay Dale; Parameter 3: KEMET
R44 R50 R61 R108 R112 R113 = RESISTOR_Dup1: PCB Footprint: R0402; Parameter 3: KEMET; Parameter 5: Vishay Dale
R47 R161 = RESISTOR_Dup1: RES SMD 0 OHM JUMPER 1/4W 1206; PartNumber: RC1206JR-070RL; Manufactur: Vishay Dale; Parameter 3: KEMET
R55 R111 R141 R143 R149 R151 = RESISTOR_Dup1: RCC0402 100 1K0 1% ET7 E3; PartNumber: RCC04021K00FKED; Manufactur: Vishay Dale; PCB Footprint: R1206; Parameter 3: KEMET
R67 R76 R87 = RESISTOR_Dup1: RCC0402 100 9K1 1% ET7 E3; PartNumber: RC0402JR-079K1L; Manufactur: Vishay Dale; PCB Footprint: R0402
R68 R74 R77 R85 R88 R93 = RESISTOR_Dup1: RC0402FR-075KL; PartNumber: RES 5K OHM 1% 1/16W 0402; Manufactur: YAGEO; PCB Footprint: R0402
R69 R78 R89 = RESISTOR_Dup1: RES 100K OHM 5% 1/4W 1206; PartNumber: CRCW1206100KJNEAC; Manufactur: YAGEO; Parameter 3: KEMET
R70 R72 R79 R84 R90 R92 = RESISTOR_Dup1: RES 5K OHM 1% 1/4W 1206; PartNumber: RT1206FRE075KL; Manufactur: YAGEO
R71 R83 R91 = RESISTOR_Dup1: RES 0R OHM 5% 1/4W 1206; PartNumber: RC1206FR-070RL; Manufactur: YAGEO
R81 = RESISTOR_Dup1: RES SMD 120 OHM 5% 1/4W 0603; PartNumber: RCS0603120RJNEA; Manufactur: Vishay Dale; Parameter 3: KEMET
R94 R95 R97 R100 R102 R104 = RESISTOR_Dup1: RES 68 OHM 1% 1/16W 0402; PartNumber: RC0402FR-0768RL; Manufactur: YAGEO; PCB Footprint: R0402
R106 R138 R146 = RESISTOR_Dup1: RCC0402 100 330R 1% ET7 E3; PartNumber: RCC0402330RFKED; Manufactur: Vishay Dale; PCB Footprint: R0402; Parameter 3: KEMET
R107 R136 R139 R144 R147 R152 = RESISTOR_Dup1: RES SMD 18K OHM 1% 1/16W 0402; PartNumber: RC0402FR-0718KL; Manufactur: YAGEO; PCB Footprint: R0402
R110 = RESISTOR_Dup1: RCC0402 100 2K0 1% ET7 E3; PartNumber: RCC04022K00FKED; Manufactur: Yageo; PCB Footprint: R0402; Parameter 3: KEMET
R115 R121 R126 = RESISTOR_Dup1: RES 0 OHM JUMPER 1/16W 0402; Manufactur: YAGEO; PartNumber: RC0402FR-070RL; PCB Footprint: R0402
T1 T2 = CMP-006-00021-2: CMC 100uH@1MHz 200MA 2LN SMD; Manufactur: Murata Electronics
U1 = CMP-0078352-1: Piccolo Microcontroller, PZ0100A (LQFP-100); Manufactur: Texas Instruments; SizeArea_mm2: 256; SizeAreaWB_mm2: 324; SizeX_mm: 16; SizeZ_mm: 1.6; CompType: IC; AEC Category: Q200; AEC Qualified: N
U2 = TPS70445PWP_TSSOP24: IC REG LINEAR 3.3V/1.2V 24HTSSOP; Manufactur: Texas Instruments
U3 = 24C16BT-I/SN: IC EEPROM 16K I2C 1MHZ 8SOIC; Manufactur: Microchip Technology; PCB Footprint: SOIC-8
U4-U8 = OPA2376AIDG4: IC OPAMP GP 2 CIRCUIT 8SOIC; Manufactur: Texas Instruments; Alternate PartNumber: Equivalent; CMRR(Min)(dB): 76; Eco-Plan: Green (RoHS & no Sb/Br); IIB(Max)(pA): 10; Iq per channel(Max)(mA): 0.95; Number of Channels: 2; Offset Drift(Typ)(uV/C): 0.32; Sub Family: Low Input Bias Current Amp (<=10pA), Low Noise Amp (<=10nV/rtHz), Low Offset Voltage Amplifier (<=500uV), Low Supply Voltage Amplifier (<=2.7V), Precision Amplifier; Total Supply Voltage(Max)(+5V is 5, +/-5V is 10): 5.5; Vio (25C)(Max)(mV): 0.025; Vn at 1kHz(Typ)(nV/rtHz): 7.5
U9 = 1050: ISO1050 ISOLATED 5-V CAN TRANSCE; Manufactur: Texas Instruments
U10 = MC74VHCT50A_SOIC14: IC BUF NON-INVERT 5.5V 14SOIC; Parameter 1: Texas Instruments
U11 = OPA2376AIDG4: IC VOLTAGE FEEDBACK 2 CIRC 8SOIC; Manufactur: Texas Instruments
U12 = OPA2376AIDG4: IC VOLTAGE FEEDBACK 2 CIRC 8SOIC; Alternate Manufacturer: Texas Instruments
Y1 = CMP-003-00030-2: 2520 10MHZ 15PF SMD; Manufactur: CTS-Frequency Controls; PartNumber: 425F35B020M0000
